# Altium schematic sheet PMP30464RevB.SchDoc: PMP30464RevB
size A3; Date: Not shown in title block; ApprovedBy: Not shown in title block; CheckedBy: Not shown in title block; Author: Not shown in title block; CompanyName: Not shown in title block; DrawnBy: M Zehendner; Engineer: Not shown in title block; Organization: Not shown in title block; Address1: Not shown in title block; Address2: Not shown in title block; Address3: Not shown in title block; Address4: Not shown in title block; DocumentNumber: 2; Revision: Use project parameter SCH_Rev; SheetNumber: 1; SheetTotal: 1; PageSetup: Record=PageOptions¦CenterHorizontal=True¦CenterVertical=True¦PrintScale=0.70¦XCorrection=1.00¦YCorrection=1.00¦PrintKind=0¦BorderSize=5000000¦LeftOffset=0¦BottomOffset=0¦Orientation=2¦PaperLength=1000¦PaperWidth=1000¦Scale=100¦PaperSource=15¦PrintQuality=600¦MediaType=1¦DitherType=10¦PaperKind=A4¦PrintScaleMode=1
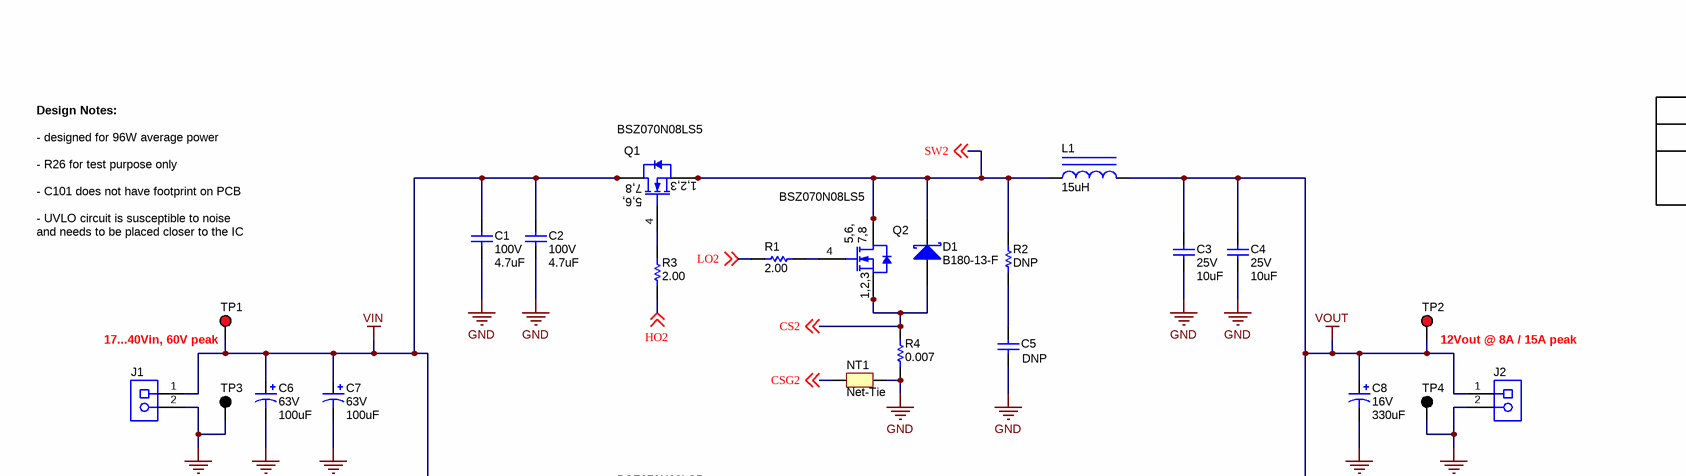
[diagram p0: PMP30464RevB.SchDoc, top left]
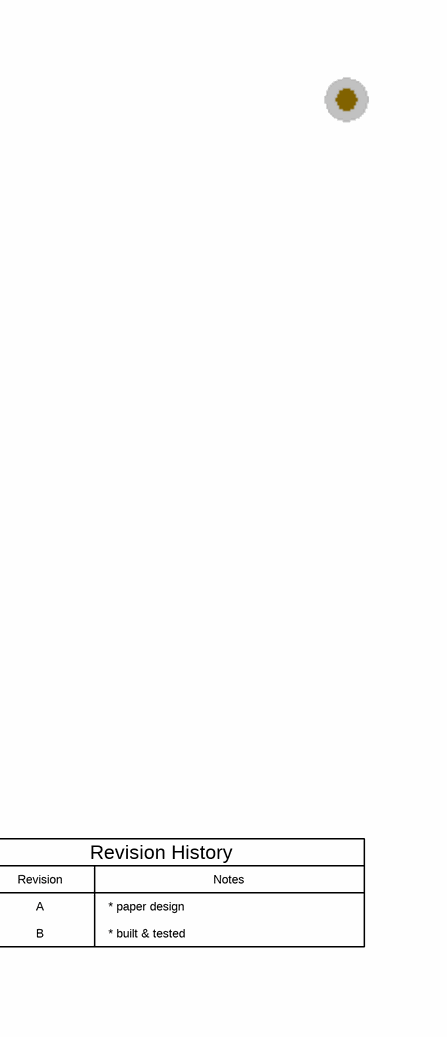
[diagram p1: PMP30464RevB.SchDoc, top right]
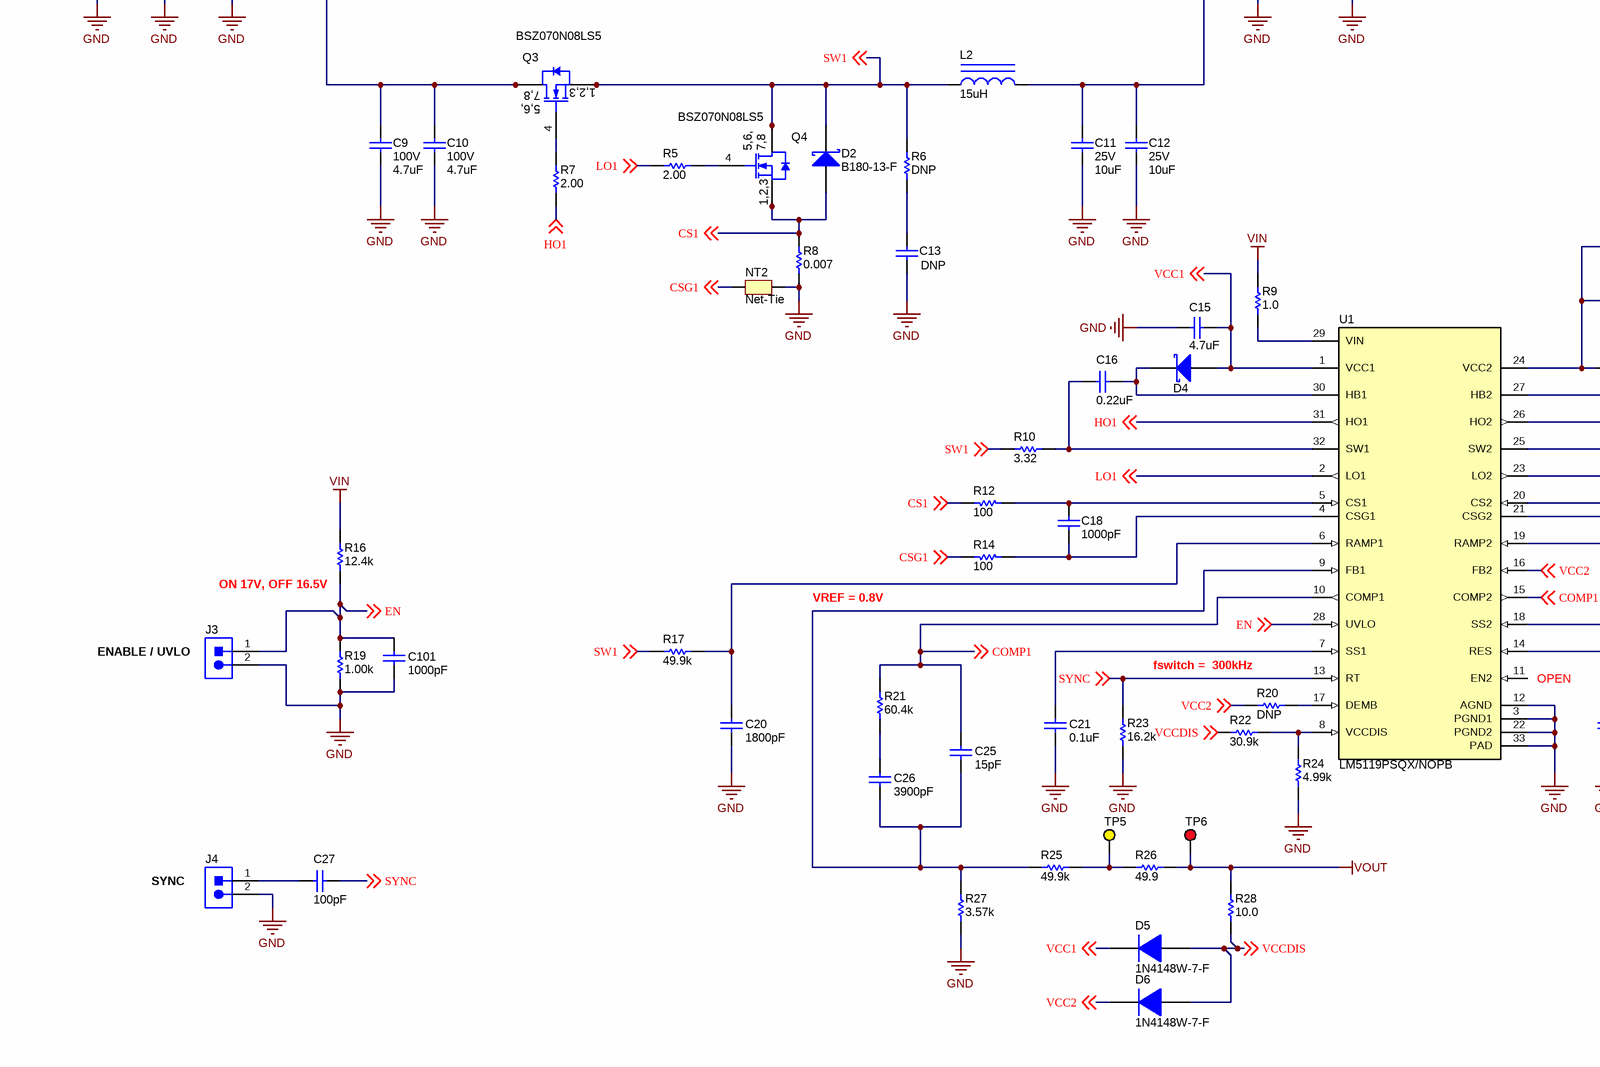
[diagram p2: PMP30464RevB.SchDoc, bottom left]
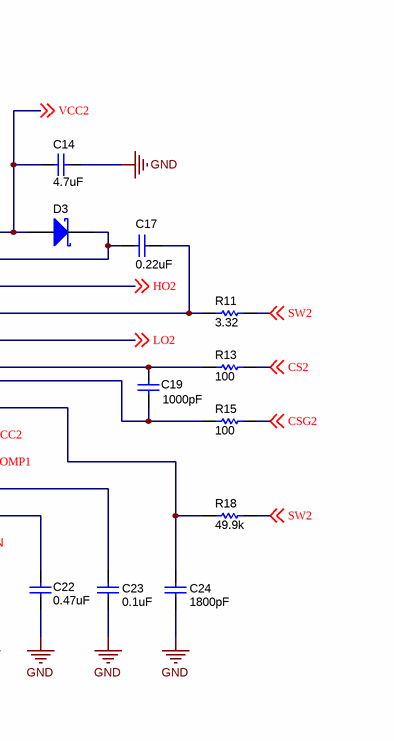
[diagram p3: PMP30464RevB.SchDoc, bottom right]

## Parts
C1  VDC_V: 100V  ValueDisplayed: 4.7uF  [1210_220]  (hidden comment: GRM32DC72A475KE01L)
C2  VDC_V: 100V  ValueDisplayed: 4.7uF  [1210_220]  (hidden comment: GRM32DC72A475KE01L)
C3  VDC_V: 25V  ValueDisplayed: 10uF  [1210_220]  (hidden comment: GRM32DR71E106KA12L)
C4  VDC_V: 25V  ValueDisplayed: 10uF  [1210_220]  (hidden comment: GRM32DR71E106KA12L)
C5  ValueDisplayed: DNP  [0603]  (hidden comment: GCM1885C2A102JA16D)
C6  VDC_V: 63V  ValueDisplayed: 100uF  [CR_1000x1270]  (hidden comment: PCR1J101MCL1GS)
C7  VDC_V: 63V  ValueDisplayed: 100uF  [CR_1000x1270]  (hidden comment: PCR1J101MCL1GS)
C8  VDC_V: 16V  ValueDisplayed: 330uF  [SM_RADIAL_10AMM]  (hidden comment: 16SVP330M)
C9  VDC_V: 100V  ValueDisplayed: 4.7uF  [1210_220]  (hidden comment: GRM32DC72A475KE01L)
C10  VDC_V: 100V  ValueDisplayed: 4.7uF  [1210_220]  (hidden comment: GRM32DC72A475KE01L)
C11  VDC_V: 25V  ValueDisplayed: 10uF  [1210_220]  (hidden comment: GRM32DR71E106KA12L)
C12  VDC_V: 25V  ValueDisplayed: 10uF  [1210_220]  (hidden comment: GRM32DR71E106KA12L)
C13  ValueDisplayed: DNP  [0603]  (hidden comment: GCM1885C2A102JA16D)
C14  ValueDisplayed: 4.7uF  [0805_HV]  (hidden comment: GRM21BR71C475KA73L)
C15  ValueDisplayed: 4.7uF  [0805_HV]  (hidden comment: GRM21BR71C475KA73L)
C16  ValueDisplayed: 0.22uF  [0603]  (hidden comment: GRM188R71H224KAC4D)
C17  ValueDisplayed: 0.22uF  [0603]  (hidden comment: GRM188R71H224KAC4D)
C18  ValueDisplayed: 1000pF  [0603]  (hidden comment: GRM188R71E102KA01D)
C19  ValueDisplayed: 1000pF  [0603]  (hidden comment: GRM188R71E102KA01D)
C20  ValueDisplayed: 1800pF  [0603]  (hidden comment: GRM188R72A182KA01D)
C21  ValueDisplayed: 0.1uF  [0603]  (hidden comment: GRM188R71H104KA93D)
C22  ValueDisplayed: 0.47uF  [0603]  (hidden comment: GRM188R71C474KA88D)
C23  ValueDisplayed: 0.1uF  [0603]  (hidden comment: GRM188R71H104KA93D)
C24  ValueDisplayed: 1800pF  [0603]  (hidden comment: GRM188R72A182KA01D)
C25  ValueDisplayed: 15pF  [0603]  (hidden comment: GRM1885C1H150JA01D)
C26  ValueDisplayed: 3900pF  [0603]  (hidden comment: GRM188R71H392KA01D)
C27  ValueDisplayed: 100pF  [0603]  (hidden comment: GRM1885C2A101JA01D)
C101  ValueDisplayed: 1000pF  [0603]  (hidden comment: GRM188R71H102JA01D)
D1  B180-13-F  [SMA]
D2  B180-13-F  [SMA]
D3  PMEG6010CEH,115  [SOD-123F]  (value not drawn)
D4  PMEG6010CEH,115  [SOD-123F]  (value not drawn)
D5  1N4148W-7-F  [SOD-123]
D6  1N4148W-7-F  [SOD-123]
J1  691236510002  [Wurth_691236510002]  (value not drawn)
J2  691236510002  [Wurth_691236510002]  (value not drawn)
J3  TSW-102-17-G-S  [Samtec_TSW-102-17-x-S]  (value not drawn)
J4  TSW-102-17-G-S  [Samtec_TSW-102-17-x-S]  (value not drawn)
L1  ValueDisplayed: 15uH  [XAL1010]  (hidden comment: XAL1010-153MEB)
L2  ValueDisplayed: 15uH  [XAL1010]  (hidden comment: XAL1010-153MEB)
NT1  Net-Tie  [NetTie_0402]  (net tie, no BOM)
NT2  Net-Tie  [NetTie_0402]  (net tie, no BOM)
Q1  BSZ070N08LS5  [PG-TSDSON-8]
Q2  BSZ070N08LS5  [PG-TSDSON-8]
Q3  BSZ070N08LS5  [PG-TSDSON-8]
Q4  BSZ070N08LS5  [PG-TSDSON-8]
R1  ValueDisplayed: 2.00  [0603]  (hidden comment: CRCW06032R00FKEA)
R2  ValueDisplayed: DNP  [0805_HV]  (hidden comment: CRCW08051R00FKEA)
R3  ValueDisplayed: 2.00  [0603]  (hidden comment: CRCW06032R00FKEA)
R4  ValueDisplayed: 0.007  [2512]  (hidden comment: CSNL2512FT7L00)
R5  ValueDisplayed: 2.00  [0603]  (hidden comment: CRCW06032R00FKEA)
R6  ValueDisplayed: DNP  [0805_HV]  (hidden comment: CRCW08051R00FKEA)
R7  ValueDisplayed: 2.00  [0603]  (hidden comment: CRCW06032R00FKEA)
R8  ValueDisplayed: 0.007  [2512]  (hidden comment: CSNL2512FT7L00)
R9  ValueDisplayed: 1.0  [0603]  (hidden comment: CRCW06031R00JNEA)
R10  ValueDisplayed: 3.32  [0603]  (hidden comment: CRCW06033R32FKEA)
R11  ValueDisplayed: 3.32  [0603]  (hidden comment: CRCW06033R32FKEA)
R12  ValueDisplayed: 100  [0603]  (hidden comment: CRCW0603100RFKEA)
R13  ValueDisplayed: 100  [0603]  (hidden comment: CRCW0603100RFKEA)
R14  ValueDisplayed: 100  [0603]  (hidden comment: CRCW0603100RFKEA)
R15  ValueDisplayed: 100  [0603]  (hidden comment: CRCW0603100RFKEA)
R16  ValueDisplayed: 12.4k  [0603]  (hidden comment: CRCW060312K4FKEA)
R17  ValueDisplayed: 49.9k  [0603]  (hidden comment: CRCW060349K9FKEA)
R18  ValueDisplayed: 49.9k  [0603]  (hidden comment: CRCW060349K9FKEA)
R19  ValueDisplayed: 1.00k  [0603]  (hidden comment: CRCW06031K00FKEA)
R20  ValueDisplayed: DNP  [0603]  (hidden comment: ERJ-3GEY0R00V)
R21  ValueDisplayed: 60.4k  [0603]  (hidden comment: CRCW060360K4FKEA)
R22  ValueDisplayed: 30.9k  [0603]  (hidden comment: CRCW060330K9FKEA)
R23  ValueDisplayed: 16.2k  [0603]  (hidden comment: CRCW060316K2FKEA)
R24  ValueDisplayed: 4.99k  [0603]  (hidden comment: CRCW06034K99FKEA)
R25  ValueDisplayed: 49.9k  [0603]  (hidden comment: CRCW060349K9FKEA)
R26  ValueDisplayed: 49.9  [0603]  (hidden comment: CRCW060349R9FKEA)
R27  ValueDisplayed: 3.57k  [0603]  (hidden comment: CRCW06033K57FKEA)
R28  ValueDisplayed: 10.0  [0603]  (hidden comment: CRCW060310R0FKEA)
TP1  5010  [Keystone5010]  (value not drawn)
TP2  5010  [Keystone5010]  (value not drawn)
TP3  5011  [Keystone5011]  (value not drawn)
TP4  5011  [Keystone5011]  (value not drawn)
TP5  5014  [Keystone5014]  (value not drawn)
TP6  5010  [Keystone5010]  (value not drawn)
U1  LM5119PSQX/NOPB  [RTV0032A]

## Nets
GND: C1.2 C2.2 C3.2 C4.2 C5.2 C6.2(-) C7.2(-) C8.2(-) C9.2 C10.2 C11.2 C12.2 C13.2 C14.1 C15.2 C20.2 C21.2 C22.1 C23.2 C24.2 C101.2 J1.2 J2.2 J3.2 J4.2 NT1.1 NT2.1 R4.1 R8.1 R19.1 R23.1 R24.1 R27.1 TP3.1 TP4.1 U1.3(PGND1) U1.12(AGND) U1.22(PGND2) U1.33(PAD)
VIN: C1.1 C2.1 C6.1(+) C7.1(+) C9.1 C10.1 J1.1 Q1.5(D) Q1.6(D) Q1.7(D) Q1.8(D) Q1.9(D) Q3.5(D) Q3.6(D) Q3.7(D) Q3.8(D) Q3.9(D) R9.2 R16.2 TP1.1
VOUT: C3.1 C4.1 C8.1(+) C11.1 C12.1 J2.1 L1.2 L2.2 R26.2 R28.2 TP2.1 TP6.1
COMP1: C25.1 R21.2 U1.10(COMP1) U1.15(COMP2) ; off-sheet COMP1
CS1: D2.2(A) Q4.1(S) Q4.2(S) Q4.3(S) R8.2 R12.2 ; off-sheet CS1
CS2: D1.2(A) Q2.1(S) Q2.2(S) Q2.3(S) R4.2 R13.2 ; off-sheet CS2
CSG1: NT2.2 R14.2 ; off-sheet CSG1
CSG2: NT1.2 R15.2 ; off-sheet CSG2
EN: C101.1 J3.1 R16.1 R19.2 U1.28(UVLO) ; off-sheet EN
HO1: R7.1 U1.31(HO1) ; off-sheet HO1
HO2: R3.1 U1.26(HO2) ; off-sheet HO2
LO1: R5.1 U1.2(LO1) ; off-sheet LO1
LO2: R1.1 U1.23(LO2) ; off-sheet LO2
SW1: D2.1(K) L2.1 Q3.1(S) Q3.2(S) Q3.3(S) Q4.5(D) Q4.6(D) Q4.7(D) Q4.8(D) Q4.9(D) R6.2 R10.1 R17.1 ; off-sheet SW1
SW2: D1.1(K) L1.1 Q1.1(S) Q1.2(S) Q1.3(S) Q2.5(D) Q2.6(D) Q2.7(D) Q2.8(D) Q2.9(D) R2.2 R11.2 R18.2 ; off-sheet SW2
SYNC: C27.1 R23.2 U1.13(RT) ; off-sheet SYNC
VCC1: C15.1 D4.2(A) D5.1(K) U1.1(VCC1) ; off-sheet VCC1
VCC2: C14.2 D3.2(A) D6.1(K) R20.2 U1.16(FB2) U1.24(VCC2) ; off-sheet VCC2
VCCDIS: D5.2(A) D6.2(A) R22.2 R28.1 ; off-sheet VCCDIS
NetC5_1: C5.1 R2.1
NetC13_1: C13.1 R6.1
NetC16_1: C16.1 D4.1(K) U1.30(HB1)
NetC16_2: C16.2 R10.2 U1.32(SW1)
NetC17_1: C17.1 R11.1 U1.25(SW2)
NetC17_2: C17.2 D3.1(K) U1.27(HB2)
NetC18_1: C18.1 R12.1 U1.5(CS1)
NetC18_2: C18.2 R14.1 U1.4(CSG1)
NetC19_1: C19.1 R13.1 U1.20(CS2)
NetC19_2: C19.2 R15.1 U1.21(CSG2)
NetC20_1: C20.1 R17.2 U1.6(RAMP1)
NetC21_1: C21.1 U1.7(SS1)
NetC22_2: C22.2 U1.14(RES)
NetC23_1: C23.1 U1.18(SS2)
NetC24_1: C24.1 R18.1 U1.19(RAMP2)
NetC25_2: C25.2 C26.2 R25.1 R27.2 U1.9(FB1)
NetC26_1: C26.1 R21.1
NetC27_2: C27.2 J4.1
NetQ1_4: Q1.4(G) R3.2
NetQ2_4: Q2.4(G) R1.2
NetQ3_4: Q3.4(G) R7.2
NetQ4_4: Q4.4(G) R5.2
NetR9_1: R9.1 U1.29(VIN)
NetR20_1: R20.1 U1.17(DEMB)
NetR22_1: R22.1 R24.2 U1.8(VCCDIS)
NetR25_2: R25.2 R26.1 TP5.1

Not connected (* = marked no-connect by the designer): U1 11(EN2)

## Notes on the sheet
- Design Notes:
- - designed for 96W average power
- - R26 for test purpose only
- Revision
- A
- * paper design
- Revision History
- Notes
- - C101 does not have footprint on PCB
- - UVLO circuit is susceptible to noise
- and needs to be placed closer to the IC
- B
- * built & tested
- (near TP1) 17...40Vin, 60V peak
- (near TP2) 12Vout @ 8A / 15A peak
- (near R16) ON 17V, OFF 16.5V
- VREF = 0.8V
- ENABLE / UVLO
- (near R20) fswitch =  300kHz
- OPEN
- SYNC

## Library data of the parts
C1 C2 C9 C10 = CMP-0009182-2: CAP, CERM, 4.7 uF, 100 V, +/- 10%, X7S, 1210; Manufacturer: MuRata; TaMin_C: -55°C; Polarized: N; SizeAreaWB_mm2: 14.7; Value1: Unknown; U/M: EA; Value: 4.7uF; TaMax_C: 125°C; SizeZ_mm: 2.2; SizeX_mm: 3.2; SizeY_mm: 2.5; Cap_Case: 1210; SizeArea_mm2: 8; Cap_F: 4.7µF; AEC Category: Q200
C3 C4 C11 C12 = CMP-0009190-2: CAP, CERM, 10 uF, 25 V, +/- 10%, X7R, 1210; Manufacturer: MuRata; TaMin_C: -55°C; Polarized: N; SizeAreaWB_mm2: 14.7; Value1: Unknown; U/M: EA; Value: 10uF; TaMax_C: 125°C; SizeZ_mm: 2.2; SizeX_mm: 3.2; SizeY_mm: 2.5; Cap_Case: 1210; SizeArea_mm2: 8; Cap_F: 10µF; AEC Category: Q200
C5 C13 = CMP-0007131-4: CAP, CERM, 1000 pF, 100 V, +/- 5%, C0G/NP0, AEC-Q200 Grade 1, 0603; Manufacturer: MuRata; TaMin_C: -55°C; Polarized: N; SizeAreaWB_mm2: 4.68; Value1: Unknown; U/M: EA; Value: 1000pF; TaMax_C: 125°C; SizeZ_mm: 1; SizeX_mm: 1.6; SizeY_mm: 0.8; Value2: 100V; SizeArea_mm2: 1.28; CompType: Capacitor; AEC Qualified: Y; Cap_F: 1nF; AEC Category: Q200
C6 C7 = CMP-0012274-3: CAP, Aluminum Polymer, 100 uF, 63 V, +/- 20%, 0.024 ohm, SMD, 2-Leads, Dia 10.5mm, Pin Spacing 8mm SMD; Manufacturer: Nichicon; TaMin_C: -55°C; ESR_ohm: 0.024; Polarized: Y; Value: 100uF; TaMax_C: 125°C; Cap_Case: 10x12.7mm; CompType: Capacitor; AEC Qualified: N; Cap_F: 100µF; IRMS_A: 3A; AEC Category: Q200
C8 = CMP-0012084-3: CAP, Aluminum Polymer, 330 uF, 16 V, +/- 20%, 0.016 ohm, 10x10.3 SMD; Manufacturer: Panasonic; TaMin_C: -55°C; ESR_ohm: 0.016; Polarized: Y; SizeAreaWB_mm2: 159.9; Value: 330uF; TaMax_C: 105°C; SizeZ_mm: 7.7; SizeX_mm: 11; SizeY_mm: 10.3; Cap_Case: 10.3x10.3x12.6; SizeArea_mm2: 113.3; CompType: Capacitor; Cap_F: 330µF; IRMS_A: 4.72A; AEC Category: Q200
C14 C15 = CMP-0008334-2: CAP, CERM, 4.7 uF, 16 V, +/- 10%, X7R, 0805; Manufacturer: MuRata; TaMin_C: -55°C; ESR_ohm: 6m; Polarized: N; SizeAreaWB_mm2: 6.75; Value1: 0.006 ohm; U/M: EA; Value: 4.7uF; TaMax_C: 125°C; SizeZ_mm: 1.45; SizeX_mm: 2; SizeY_mm: 1.25; Cap_Case: 0805; Value2: 16V; SizeArea_mm2: 2.5; CompType: Capacitor; Cap_F: 4.7µF; AEC Category: Q200
C16 C17 = CMP-0007445-4: CAP, CERM, 0.22 uF, 50 V, +/- 10%, X7R, 0603; Manufacturer: MuRata; TaMin_C: -55°C; Polarized: N; SizeAreaWB_mm2: 4.68; Value1: Unknown; U/M: EA; Value: 0.22uF; TaMax_C: 125°C; SizeZ_mm: 1; SizeX_mm: 1.6; SizeY_mm: 0.8; Value2: 50V; SizeArea_mm2: 1.28; CompType: Capacitor; Cap_F: 220nF; AEC Category: Q200
C18 C19 = CMP-0007402-2: CAP, CERM, 1000 pF, 25 V, +/- 10%, X7R, 0603; Manufacturer: MuRata; TaMin_C: -55°C; Polarized: N; SizeAreaWB_mm2: 4.68; Value1: Unknown; U/M: EA; Value: 1000pF; TaMax_C: 125°C; SizeZ_mm: 1; SizeX_mm: 1.6; SizeY_mm: 0.8; Value2: 25V; SizeArea_mm2: 1.28; Cap_F: 1nF; AEC Category: Q200
C20 C24 = CMP-0007473-4: CAP, CERM, 1800 pF, 100 V, +/- 10%, X7R, 0603; Manufacturer: MuRata; TaMin_C: -55°C; Polarized: N; SizeAreaWB_mm2: 4.68; Value1: Unknown; U/M: EA; Value: 1800pF; TaMax_C: 125°C; SizeZ_mm: 1; SizeX_mm: 1.6; SizeY_mm: 0.8; Value2: 100V; SizeArea_mm2: 1.28; CompType: Capacitor; Cap_F: 1.8nF; AEC Category: Q200
C21 C23 = CMP-0007434-4: CAP, CERM, 0.1 uF, 50 V, +/- 10%, X7R, 0603; Manufacturer: MuRata; TaMin_C: -55°C; Polarized: N; SizeAreaWB_mm2: 4.68; Value1: Unknown; U/M: EA; Value: 0.1uF; TaMax_C: 125°C; SizeZ_mm: 1; SizeX_mm: 1.6; SizeY_mm: 0.8; Value2: 50V; SizeArea_mm2: 1.28; CompType: Capacitor; Cap_F: 100nF; AEC Category: Q200
C22 = CMP-0007398-2: CAP, CERM, 0.47 uF, 16 V, +/- 10%, X7R, 0603; Manufacturer: MuRata; TaMin_C: -55°C; Polarized: N; SizeAreaWB_mm2: 4.68; Value1: Unknown; U/M: EA; Value: 0.47uF; TaMax_C: 125°C; SizeZ_mm: 1; SizeX_mm: 1.6; SizeY_mm: 0.8; Value2: 16V; SizeArea_mm2: 1.28; CompType: Capacitor; Cap_F: 470nF; AEC Category: Q200
C25 = CMP-0007184-4: CAP, CERM, 15 pF, 50 V, +/- 5%, C0G/NP0, 0603; Manufacturer: MuRata; TaMin_C: -55°C; Polarized: N; SizeAreaWB_mm2: 4.68; Value1: Unknown; U/M: EA; Value: 15pF; TaMax_C: 125°C; SizeZ_mm: 1; SizeX_mm: 1.6; SizeY_mm: 0.8; Value2: 50V; SizeArea_mm2: 1.28; CompType: Capacitor; AEC Category: Q200
C26 = CMP-0007453-4: CAP, CERM, 3900 pF, 50 V, +/- 10%, X7R, 0603; Manufacturer: MuRata; TaMin_C: -55°C; Polarized: N; SizeAreaWB_mm2: 4.68; Value1: Unknown; U/M: EA; Value: 3900pF; TaMax_C: 125°C; SizeZ_mm: 1; SizeX_mm: 1.6; SizeY_mm: 0.8; Value2: 50V; SizeArea_mm2: 1.28; CompType: Capacitor; Cap_F: 3.9nF; AEC Category: Q200
C27 = CMP-0007237-4: CAP, CERM, 100 pF, 100 V, +/- 5%, C0G/NP0, 0603; Manufacturer: MuRata; TaMin_C: -55°C; Polarized: N; SizeAreaWB_mm2: 4.68; Value1: Unknown; U/M: EA; Value: 100pF; TaMax_C: 125°C; SizeZ_mm: 1; SizeX_mm: 1.6; SizeY_mm: 0.8; Value2: 100V; SizeArea_mm2: 1.28; CompType: Capacitor; AEC Category: Q200
C101 = CMP-0007431-4: CAP, CERM, 1000 pF, 50 V, +/- 5%, X7R, 0603; Manufacturer: MuRata; TaMin_C: -55°C; Polarized: N; SizeAreaWB_mm2: 4.68; Value1: Unknown; U/M: EA; Value: 1000pF; TaMax_C: 125°C; SizeZ_mm: 1; SizeX_mm: 1.6; SizeY_mm: 0.8; Value2: 50V; SizeArea_mm2: 1.28; CompType: Capacitor; Cap_F: 1nF; AEC Category: Q200
D1 D2 = CMP-0028393-1: Diode, Schottky, 80 V, 1 A, SMA; Manufacturer: Diodes Inc.; Io_A: 1A; Green_Lifecycle: Not Set; SizeAreaWB_mm2: 37.3428; Vr_V: 80V; Green_REACh: Incomplete; TJmax_C: 150°C; U/M: EA; Value: 80V; SizeZ_mm: 2.87; SizeX_mm: 5.59; SizeY_mm: 2.92; Vf_V: 7.9dV; Value2: 0.79V; SizeArea_mm2: 16.3228; AEC Category: Q101; RJC_CperW: 25
D3 D4 = CMP-0028377-1: Diode, Schottky, 60 V, 1 A, SOD-123F; Manufacturer: Nexperia; Io_A: 1A; Green_Lifecycle: Not Set; SizeAreaWB_mm2: 11.7; Vr_V: 60V; Green_REACh: Incomplete; TJmax_C: 150°C; U/M: EA; Value: 60V; SizeZ_mm: 1.1; SizeX_mm: 3.5; SizeY_mm: 1.6; Vf_V: 5.7dV; Value2: 0.57V; SizeArea_mm2: 5.6; AEC Category: Q101
D5 D6 = CMP-0029001-1: Diode, Ultrafast, 100 V, 0.15 A, SOD-123; Manufacturer: Diodes Inc.; Io_A: 1.5dA; Green_Lifecycle: Active; SizeAreaWB_mm2: 13.095; Vr_V: 100V; Green_REACh: Passed; Value1: 0.15A; TJmax_C: 150°C; U/M: EA; Value: 100V; SizeZ_mm: 1.35; SizeX_mm: 3.85; SizeY_mm: 1.7; Vf_V: 1.25V; SizeArea_mm2: 6.545; AEC Category: Q101
J1 J2 = CMP-0079044-1: Terminal Block, 5.08mm, 2x1, R/A, TH; Manufacturer: Wurth Elektronik; Pitch_mm: 5.08; Cert_VDE: Y; Gender: Female; Voltage_V: 300V; Current_A: 20A; Row_Count: 1
J3 J4 = CMP-0077742-1: Header, 2.54mm, 2x1, Gold, TH; Manufacturer: Samtec; Pitch_mm: 2.54; Gender: Male; Cert_CSA: Y; Shrouded: N; Row_Count: 1
L1 L2 = CMP-0061645-2: Inductor, Shielded, Composite, 15 uH, 13.8 A, 0.02 ohm, SMD; Manufacturer: Coilcraft; Isat: 15.5A @ 30% inductance drop; Irms: 13.8A @ 40C rise; Green_Lifecycle: Not Set; SizeAreaWB_mm2: 159.6; DCR_ohm: 0.02; Green_REACh: Incomplete; Value: 15uH; Imax_A: 13.8A; SizeZ_mm: 10; SizeX_mm: 11.3; SizeArea_mm2: 113; Ind_H: 15µH; AEC Category: Q200
NT1 NT2 = CMP-0078142-1: Single point connection between nets.
Q1-Q4 = CMP-0000792-1: MOSFET, N-CH, 60 V, 17 A, PG-TSDSON-8; Alternate Manufacturer: None; Manufacturer: Infineon Technologies; SizeZ_mm: 1.1; ChType: N; Value2: 27 nC; VdsMax_V: 60V; SizeX_mm: 3.4; SizeAreaWB_mm2: 19.36; Vgs_V: 20V; QgTyp_nC: 27; Value: 60V; SizeArea_mm2: 11.56; AEC Category: Q101; IdsMax_A: 17A; U/M: EA
R1 R3 R5 R7 = CMP-0022302-4: RES, 2.00, 1%, 0.1 W, AEC-Q200 Grade 0, 0603; Manufacturer: Vishay-Dale; Power_W: 100mW; TempCo: 100 ppm/C; Value_Code: 2R00; Value: 2.00; EIA_Code: E96; Res_ohm: 2; SizeX_mm: 1.6; SizeY_mm: 0.8; SizeZ_mm: 1; Value2: 0.1W; SizeArea_mm2: 1.28; AEC Qualified: Y; VDC_V: 75V; AEC Category: Q200; AEC Grade: 0
R2 R6 = CMP-0021009-3: RES, 1.00, 1%, 0.125 W, AEC-Q200 Grade 0, 0805; Manufacturer: Vishay-Dale; Power_W: 125mW; TempCo: 100 ppm/C; Value_Code: 1R00; Value: 1.00; EIA_Code: E96; Res_ohm: 1; SizeX_mm: 2; SizeY_mm: 1.25; SizeZ_mm: 1.45; Value2: 0.125W; SizeArea_mm2: 2.5; AEC Qualified: Y; VDC_V: 150V; AEC Category: Q200; AEC Grade: 0
R4 R8 = CMP-0015759-2: RES, 0.007, 1%, 2 W, 2512; Manufacturer: Stackpole Electronics Inc; Power_W: 2W; TempCo: 50 ppm/C; Value_Code: 7L000; U/M: EA; Value: 0.007; EIA_Code: E96; Res_ohm: 7m; SizeX_mm: 6.3; SizeY_mm: 3.2; SizeZ_mm: 0.71; SizeArea_mm2: 20.16; AEC Category: Q200
R9 = CMP-0025743-2: RES, 1.0, 5%, 0.1 W, 0603; Manufacturer: Vishay-Dale; Power_W: 100mW; TempCo: 200 ppm/C; Value_Code: 1R00; U/M: EA; Value: 1.0; EIA_Code: E24; Res_ohm: 1; SizeX_mm: 1.6; SizeY_mm: 0.8; Value2: 0.1W; SizeArea_mm2: 1.28; VDC_V: 75V; AEC Category: Q200
R10 R11 = CMP-0022400-4: RES, 3.32, 1%, 0.1 W, AEC-Q200 Grade 0, 0603; Manufacturer: Vishay-Dale; Power_W: 100mW; TempCo: 100 ppm/C; Value_Code: 3R32; Value: 3.32; EIA_Code: E96; SizeX_mm: 1.6; SizeY_mm: 0.8; SizeZ_mm: 1; Value2: 0.1W; SizeArea_mm2: 1.28; AEC Qualified: Y; VDC_V: 75V; AEC Category: Q200; AEC Grade: 0
R12-R15 = CMP-0021991-2: RES, 100, 1%, 0.1 W, 0603; Manufacturer: Vishay-Dale; Power_W: 100mW; TempCo: 100 ppm/C; Value_Code: 100R; U/M: EA; Value: 100; EIA_Code: E96; SizeX_mm: 1.6; SizeY_mm: 0.8; SizeZ_mm: 1; Value2: 0.1W; SizeArea_mm2: 1.28; VDC_V: 75V; AEC Category: Q200
R16 = CMP-0022031-4: RES, 12.4 k, 1%, 0.1 W, AEC-Q200 Grade 0, 0603; Manufacturer: Vishay-Dale; Power_W: 100mW; TempCo: 100 ppm/C; Value_Code: 12k4; Value: 12.4k; EIA_Code: E96; SizeX_mm: 1.6; SizeY_mm: 0.8; SizeZ_mm: 1; Value2: 0.1W; SizeArea_mm2: 1.28; AEC Qualified: Y; VDC_V: 75V; AEC Category: Q200; AEC Grade: 0
R17 R18 R25 = CMP-0022447-4: RES, 49.9 k, 1%, 0.1 W, AEC-Q200 Grade 0, 0603; Manufacturer: Vishay-Dale; Power_W: 100mW; TempCo: 100 ppm/C; Value_Code: 49k9; Value: 49.9k; EIA_Code: E96; SizeX_mm: 1.6; SizeY_mm: 0.8; SizeZ_mm: 1; Value2: 0.1W; SizeArea_mm2: 1.28; AEC Qualified: Y; VDC_V: 75V; AEC Category: Q200; AEC Grade: 0
R19 = CMP-0022109-5: RES, 1.00 k, 1%, 0.1 W, AEC-Q200 Grade 0, 0603; Manufacturer: Vishay-Dale; Power_W: 100mW; TempCo: 100 ppm/C; Value_Code: 1k00; Value: 1.00k; EIA_Code: E96; Res_ohm: 1k; SizeX_mm: 1.6; SizeY_mm: 0.8; SizeZ_mm: 1; Value2: 0.1W; SizeArea_mm2: 1.28; AEC Qualified: Y; VDC_V: 75V; AEC Category: Q200; AEC Grade: 0
R20 = CMP-0025874-2: RES, 0, 5%, 0.1 W, 0603; Manufacturer: Panasonic; Power_W: 100mW; TempCo: 600 ppm/C; Value_Code: 0000; U/M: EA; Value: 0; EIA_Code: E24; SizeX_mm: 1.6; SizeY_mm: 0.8; SizeZ_mm: 1; Value2: 0.1W; SizeArea_mm2: 1.28; VDC_V: 50V; AEC Category: Q200
R21 = CMP-0022532-4: RES, 60.4 k, 1%, 0.1 W, AEC-Q200 Grade 0, 0603; Manufacturer: Vishay-Dale; Power_W: 100mW; TempCo: 100 ppm/C; Value_Code: 60k4; Value: 60.4k; EIA_Code: E96; SizeX_mm: 1.6; SizeY_mm: 0.8; SizeZ_mm: 1; Value2: 0.1W; SizeArea_mm2: 1.28; AEC Qualified: Y; VDC_V: 75V; AEC Category: Q200; AEC Grade: 0
R22 = CMP-0022325-4: RES, 30.9 k, 1%, 0.1 W, AEC-Q200 Grade 0, 0603; Manufacturer: Vishay-Dale; Power_W: 100mW; TempCo: 100 ppm/C; Value_Code: 30k9; Value: 30.9k; EIA_Code: E96; SizeX_mm: 1.6; SizeY_mm: 0.8; SizeZ_mm: 1; Value2: 0.1W; SizeArea_mm2: 1.28; AEC Qualified: Y; VDC_V: 75V; AEC Category: Q200; AEC Grade: 0
R23 = CMP-0022079-4: RES, 16.2 k, 1%, 0.1 W, AEC-Q200 Grade 0, 0603; Manufacturer: Vishay-Dale; Power_W: 100mW; TempCo: 100 ppm/C; Value_Code: 16k2; Value: 16.2k; EIA_Code: E96; SizeX_mm: 1.6; SizeY_mm: 0.8; SizeZ_mm: 1; Value2: 0.1W; SizeArea_mm2: 1.28; AEC Qualified: Y; VDC_V: 75V; AEC Category: Q200; AEC Grade: 0
R24 = CMP-0022458-4: RES, 4.99 k, 1%, 0.1 W, AEC-Q200 Grade 0, 0603; Manufacturer: Vishay-Dale; Power_W: 100mW; TempCo: 100 ppm/C; Value_Code: 4k99; Value: 4.99k; EIA_Code: E96; SizeX_mm: 1.6; SizeY_mm: 0.8; SizeZ_mm: 1; Value2: 0.1W; SizeArea_mm2: 1.28; AEC Qualified: Y; VDC_V: 75V; AEC Category: Q200; AEC Grade: 0
R26 = CMP-0022448-4: RES, 49.9, 1%, 0.1 W, AEC-Q200 Grade 0, 0603; Manufacturer: Vishay-Dale; Power_W: 100mW; TempCo: 100 ppm/C; Value_Code: 49R9; Value: 49.9; EIA_Code: E96; SizeX_mm: 1.6; SizeY_mm: 0.8; SizeZ_mm: 1; Value2: 0.1W; SizeArea_mm2: 1.28; AEC Qualified: Y; VDC_V: 75V; AEC Category: Q200; AEC Grade: 0
R27 = CMP-0022378-4: RES, 3.57 k, 1%, 0.1 W, AEC-Q200 Grade 0, 0603; Manufacturer: Vishay-Dale; Power_W: 100mW; TempCo: 100 ppm/C; Value_Code: 3k57; Value: 3.57k; EIA_Code: E96; SizeX_mm: 1.6; SizeY_mm: 0.8; SizeZ_mm: 1; Value2: 0.1W; SizeArea_mm2: 1.28; AEC Qualified: Y; VDC_V: 75V; AEC Category: Q200; AEC Grade: 0
R28 = CMP-0022003-4: RES, 10.0, 1%, 0.1 W, AEC-Q200 Grade 0, 0603; Manufacturer: Vishay-Dale; Power_W: 100mW; TempCo: 100 ppm/C; Value_Code: 10R0; Value: 10.0; EIA_Code: E96; Res_ohm: 10; SizeX_mm: 1.6; SizeY_mm: 0.8; SizeZ_mm: 1; Value2: 0.1W; SizeArea_mm2: 1.28; AEC Qualified: Y; VDC_V: 75V; AEC Category: Q200; AEC Grade: 0
TP1 TP2 TP6 = CMP-0055147-1: Test Point, Multipurpose, Red, TH; Manufacturer: Keystone; CNHeader: FALSE; Green_Lifecycle: Active; Green_REACh: Passed; ContactFinish: Silver; CT: TRUE
TP3 TP4 = CMP-0055148-1: Test Point, Multipurpose, Black, TH; Manufacturer: Keystone; CNHeader: FALSE; Green_Lifecycle: Active; Green_REACh: Passed; ContactFinish: Silver; CT: TRUE
TP5 = CMP-0055151-1: Test Point, Multipurpose, Yellow, TH; Manufacturer: Keystone; CNHeader: FALSE; Green_Lifecycle: Active; Green_REACh: Passed; ContactFinish: Silver; CT: TRUE
U1 = CMP-0066051-1: 5.5-65V Wide Vin, Current Mode Dual Synchronous Buck Controller, RTV0032A (WQFN-32); Alternate PartNumber: LM5119PSQ/NOPB; Alternate Manufacturer: Texas Instruments; SizeAreaWB_mm2: 49.0; U/M: EA; SizeZ_mm: 0.8; SizeX_mm: 5.0; SizeArea_mm2: 25.0; CompType: IC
